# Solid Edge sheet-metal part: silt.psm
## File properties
Author: Cymax
Template: Normal.psm
Last saved by: Cymax
Revision: 13
Application: Solid Edge
Accuracy: 0,990
Material Thickness: 0,00 m
Bend Radius: 0,00 m
Relief Width: 0,00 m
Relief Length: 0,00 m
Neutral Factor: 0,330
Minimum Arc Length: 0,00 m
Deviational Tolerance: 0,00 m
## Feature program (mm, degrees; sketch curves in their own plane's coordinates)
base tab "unnamed BaseTab 1"
flange "Flange_1"
flange "Flange_2"
jog tab "JogTab_4"  OffsetDistance = 50 mm
jog tab "JogTab_5"  OffsetDistance = 50 mm
flange "Flange_5"
flange "Flange_6"
bead "unnamed Bead 1"
mirror "unnamed Mirror 1" of "unnamed Bead 1" about plane through (0, 0, 0) normal (1, 0, 0)
bead "unnamed Bead 2"
louver "Louver_2"  LouverDepth = 10 mm; LouverHeight = 5 mm
mirror "unnamed Mirror 2" of "Louver_2" about plane through (0, 0, 0) normal (1, 0, 0)
louver "unnamed Louver 1"
dimple "Dimple_2"
dimple "Dimple_3"
dimple "Dimple_4"
dimple "Dimple_5"
dimple "Dimple_7"
drawn cutout "DrawnCutout_2"
mirror "unnamed Mirror 3" of "DrawnCutout_2" about plane through (0, 0, 0) normal (1, 0, 0)
drawn cutout "unnamed DrawnCutout 1"
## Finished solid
Body 1: solid body, 290 faces, 686 edges, 410 vertices.
  Faces by surface: plane 142, cylinder 114, torus 18, sphere 16
  Edges by curve: line 478, circle 120, ellipse 86, intersection 2
Bounding box of the edges (mm; curved faces can reach further): 602.000 x 100.000 x 62.000, from (-301, -50, -11) to (301, 50, 51).
Cylindrical faces by radius (mm): R1 x96, R2 x8, R11.5 x2, R12.5 x2, R13.4181 x1, R14.4181 x1, R15 x2, R16 x2
Toroidal faces (ring radius, tube radius in mm): R13.4181 r1 x1, R14.4181 r1 x1, R17 r1 x2, R17 r2 x2, R17.8885 r1 x4, R27.2751 r1 x2, R45.1636 r20 x2, R45.1636 r21 x2, R63.0522 r1 x2
Spherical faces by radius (mm): R11.5 x4, R12.5 x4, R20 x4, R21 x4
Planar faces by outward normal: +x 16, +y 25, +z 14, -x 16, -y 25, -z 8, oblique 38
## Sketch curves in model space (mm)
line (-300, 0, 51) -> (300, 0, 51)
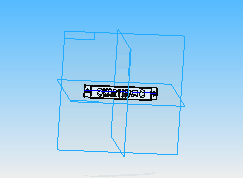
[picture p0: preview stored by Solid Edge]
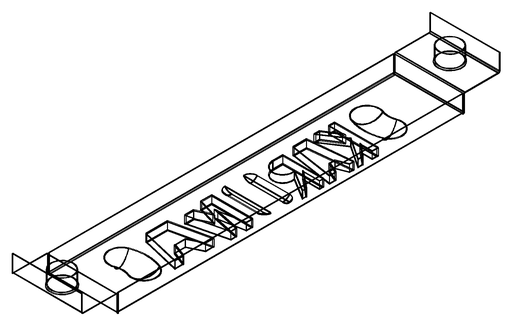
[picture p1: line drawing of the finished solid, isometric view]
